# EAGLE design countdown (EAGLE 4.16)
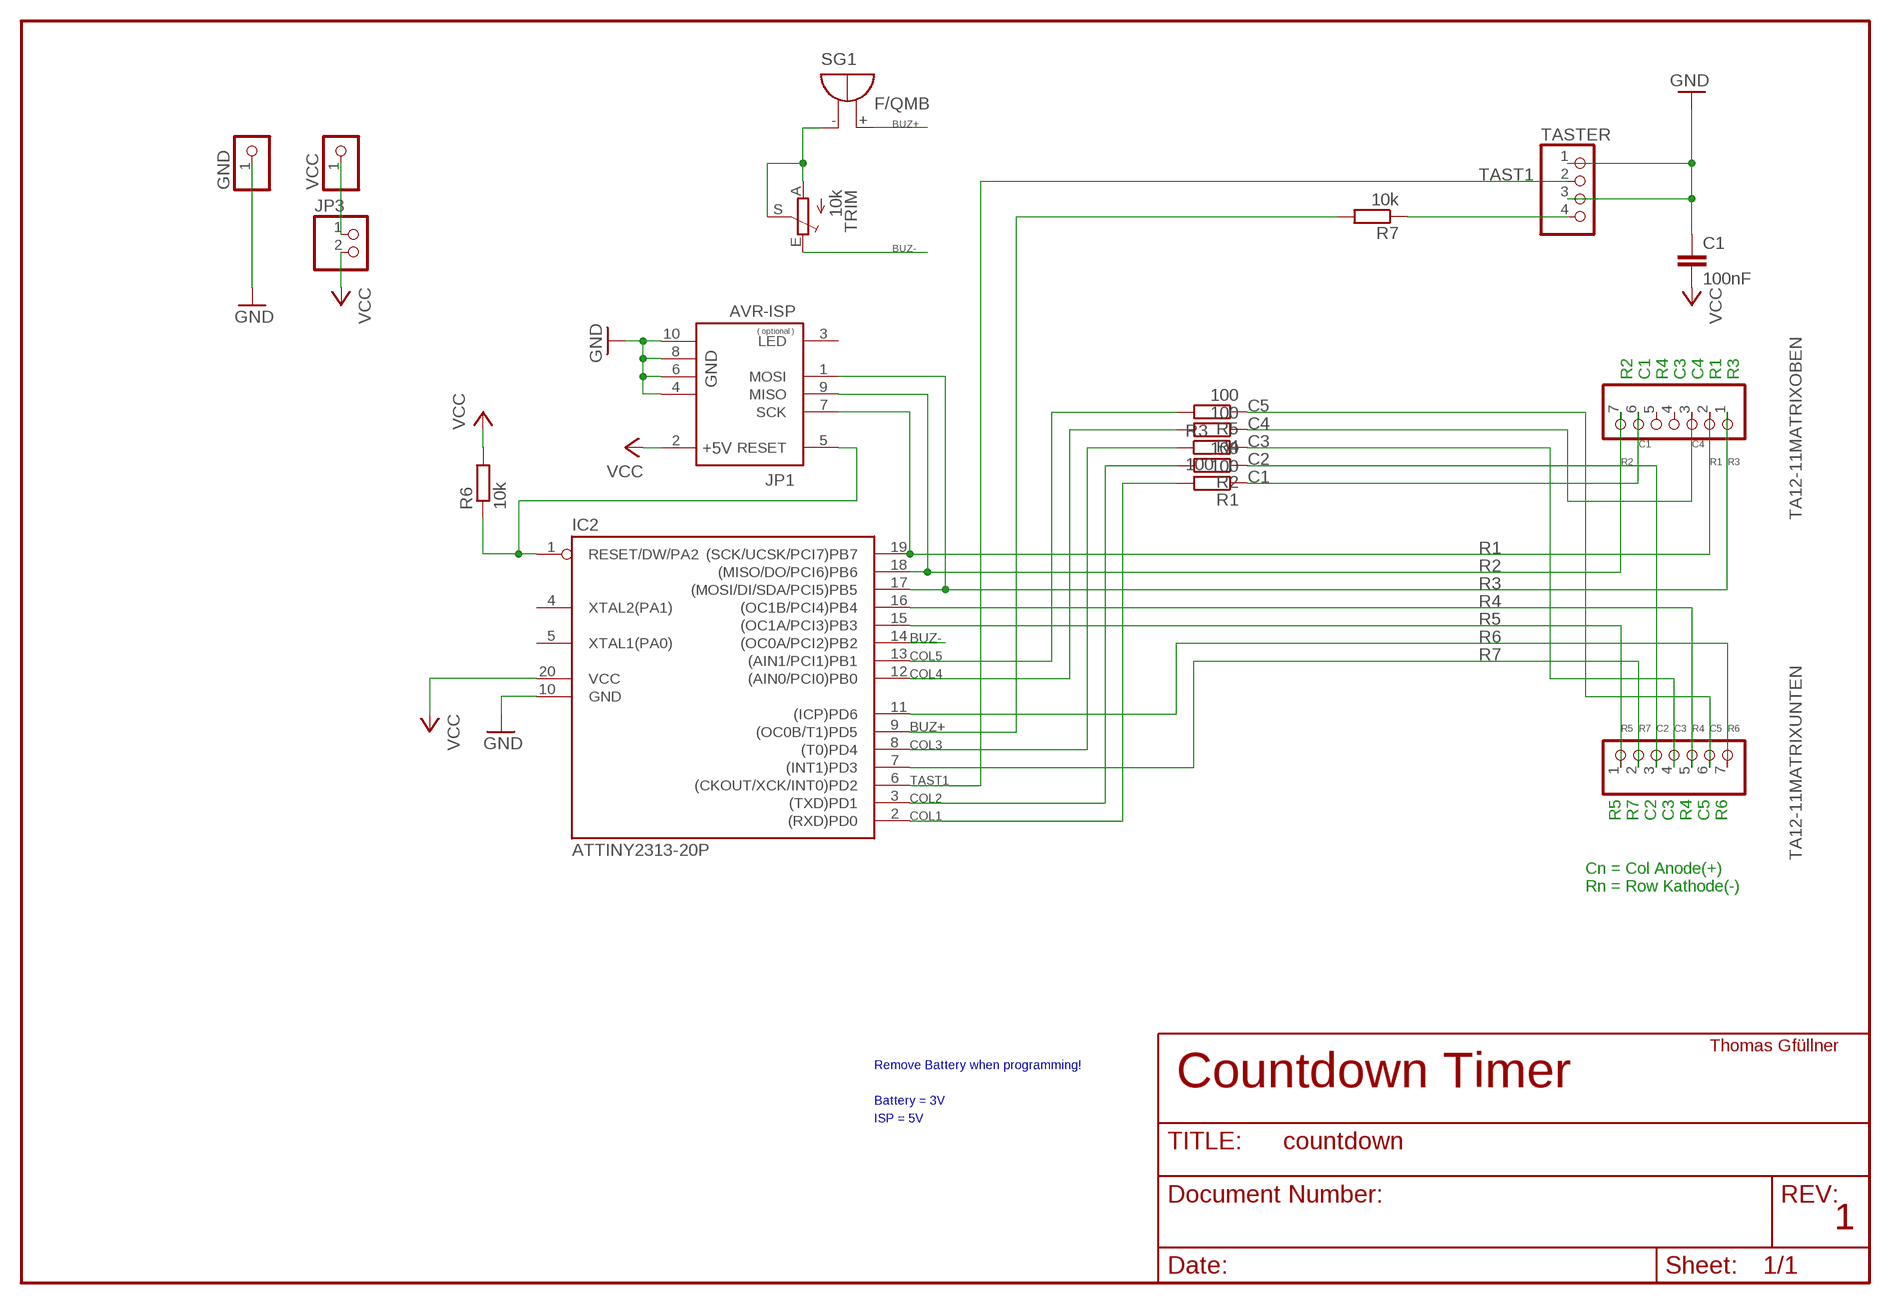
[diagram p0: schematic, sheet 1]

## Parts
C1  100nF  C-EU050-025X075  [C050-025X075]
GND  PINHD-1X1  [1X01]
IC2  ATTINY2313-20P  [DIL20]
JP1  AVR-ISP  [ML10]
JP3  PINHD-1X2  [1X02]
R1  100  R-EU_0207/12  [0207/12]
R2  100  R-EU_0207/12  [0207/12]
R3  100  R-EU_0204/7  [0204/7]
R4  100  R-EU_0207/12  [0207/12]
R5  100  R-EU_0207/12  [0207/12]
R6  10k  R-EU_0204/7  [0204/7]
R7  10k  R-EU_0207/12  [0207/12]
SG1  F/QMB  [F/QMB]
TA12-11MATRIXOBEN  PINHD-1X7  [1X07]
TA12-11MATRIXUNTEN  PINHD-1X7  [1X07]
TASTER  PINHD-1X4  [1X04]
TRIM  10k  TRIM_EU-S75H  [S75H]
VCC  PINHD-1X1  [1X01]

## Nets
BUZ+: IC2.9((OC0B/T1)PD5) R7.2 SG1.+(-)
BUZ-: IC2.14((OC0A/PCI2)PB2) TRIM.E
C1: R1.1 TA12-11MATRIXOBEN.6
C2: R2.1 TA12-11MATRIXUNTEN.3
C3: R3.2 TA12-11MATRIXUNTEN.4
C4: R4.1 TA12-11MATRIXOBEN.3
C5: R5.1 TA12-11MATRIXUNTEN.6
COL1: IC2.2((RXD)PD0) R1.2
COL2: IC2.3((TXD)PD1) R2.2
COL3: IC2.8((T0)PD4) R3.1
COL4: IC2.12((AIN0/PCI0)PB0) R4.2
COL5: IC2.13((AIN1/PCI1)PB1) R5.2
GND: C1.1 GND.1 IC2.10(GND) JP1.4(GND) JP1.6(GND) JP1.8(GND) JP1.10(GND) TASTER.1 TASTER.3
N$7: SG1.-(+) TRIM.A TRIM.S
N$9: IC2.1(RESET/DW/PA2) JP1.5(RESET) R6.1
N$10: R7.1 TASTER.4
N$27: JP3.1 VCC.1
R1: IC2.19((SCK/UCSK/PCI7)PB7) JP1.7(SCK) TA12-11MATRIXOBEN.2
R2: IC2.18((MISO/DO/PCI6)PB6) JP1.9(MISO) TA12-11MATRIXOBEN.7
R3: IC2.17((MOSI/DI/SDA/PCI5)PB5) JP1.1(MOSI) TA12-11MATRIXOBEN.1
R4: IC2.16((OC1B/PCI4)PB4) TA12-11MATRIXUNTEN.5
R5: IC2.15((OC1A/PCI3)PB3) TA12-11MATRIXUNTEN.1
R6: IC2.11((ICP)PD6) TA12-11MATRIXUNTEN.7
R7: IC2.7((INT1)PD3) TA12-11MATRIXUNTEN.2
TAST1: IC2.6((CKOUT/XCK/INT0)PD2) TASTER.2
VCC: C1.2 IC2.20(VCC) JP1.2(+5V) JP3.2 R6.2
Unconnected: IC2.4(XTAL2(PA1)) IC2.5(XTAL1(PA0)) JP1.3(LED) TA12-11MATRIXOBEN.4 TA12-11MATRIXOBEN.5

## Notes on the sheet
- R2 | C1 | R4 | C3 | C4 | R1 | R3
- R5 | R7 | C2 | C3 | R4 | C5 | R6
- Cn = Col Anode(+)
- Rn = Row Kathode(-)
- Thomas Gfüllner
- Remove Battery when programming!
- Countdown Timer
- Battery = 3V
- ISP = 5V
- 1

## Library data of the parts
C1 = rcl:C-EU: CAPACITOR, European symbol
GND VCC = pinhead:PINHD-1X1: PIN HEADER
IC2 = avr:ATTINY2313: MICROCONTROLLER 2 Kbytes FLASH 128 bytes SRAM 128 bytes EEPROM USART USI
JP1 = roboternetz-definitionen:AVR-ISP: ISP ( In System Programming ) Stecker für AVRs Über diesen Anschluß kann ein AVR mit einem Standard ISP-Kabel direkt an einen Parallelport des PC´s angeschlossen und programmiert werden. Die Belegung des ISP-Anschlusses ist zu dem weit verbreitetet STK200 Programmier Dongle kompatibel. Ein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
JP3 = pinhead:PINHD-1X2: PIN HEADER
R1-R7 = rcl:R-EU_: RESISTOR, European symbol
SG1 = buzzer:F/QMB: BUZZER
TA12-11MATRIXOBEN TA12-11MATRIXUNTEN = pinhead:PINHD-1X7: PIN HEADER
TASTER = pinhead:PINHD-1X4: PIN HEADER
TRIM = pot:TRIM_EU-: POTENTIOMETER

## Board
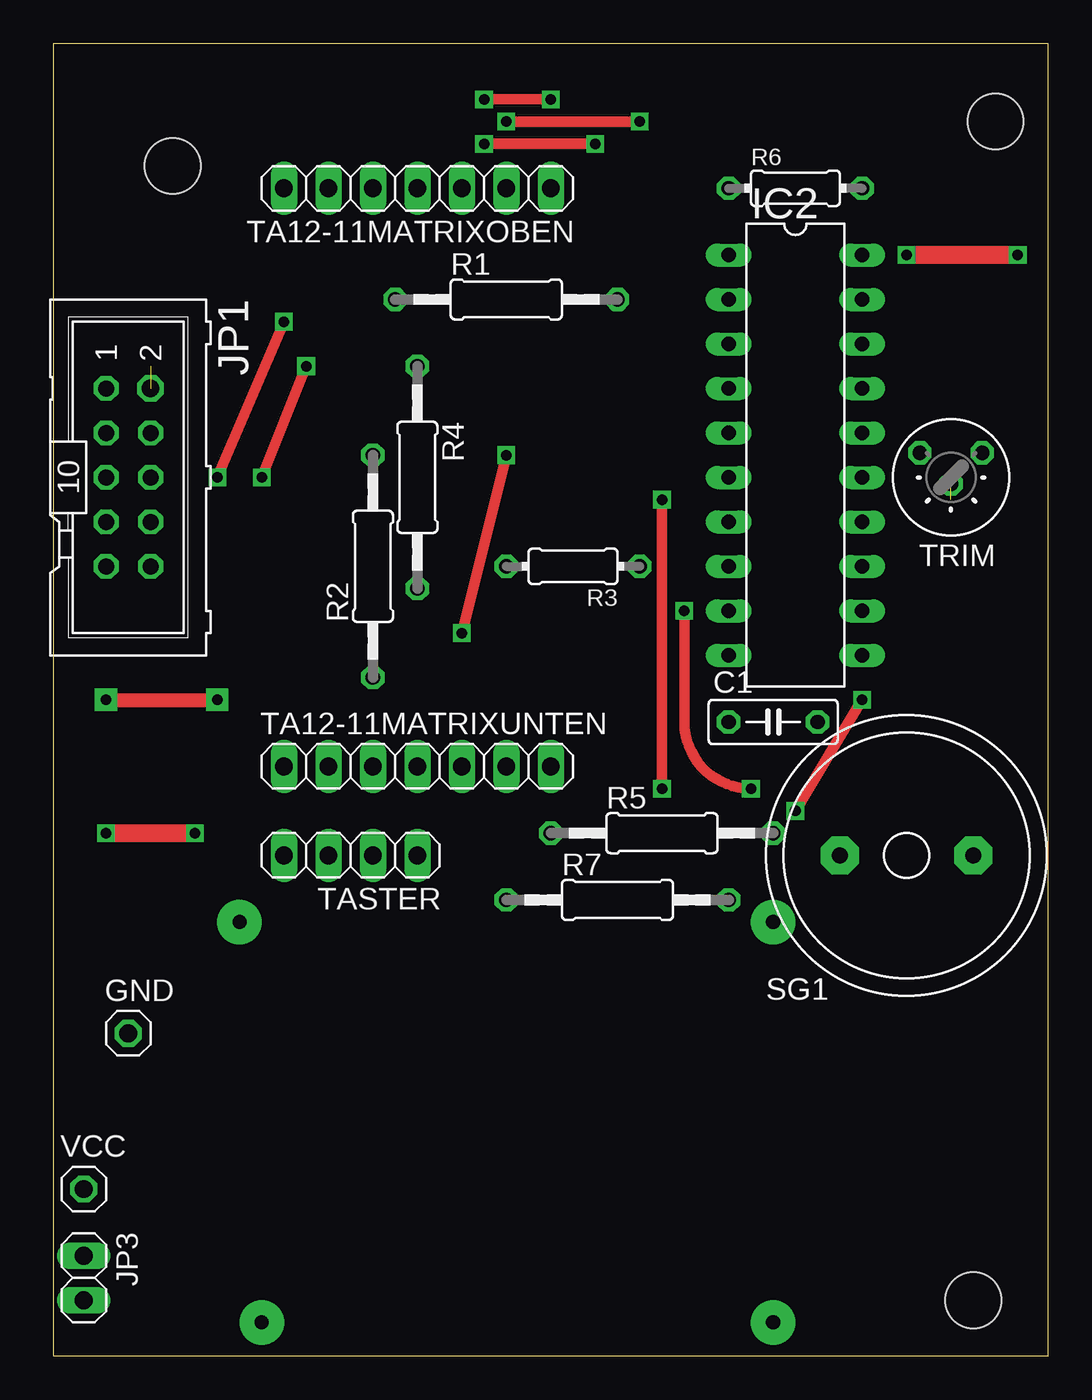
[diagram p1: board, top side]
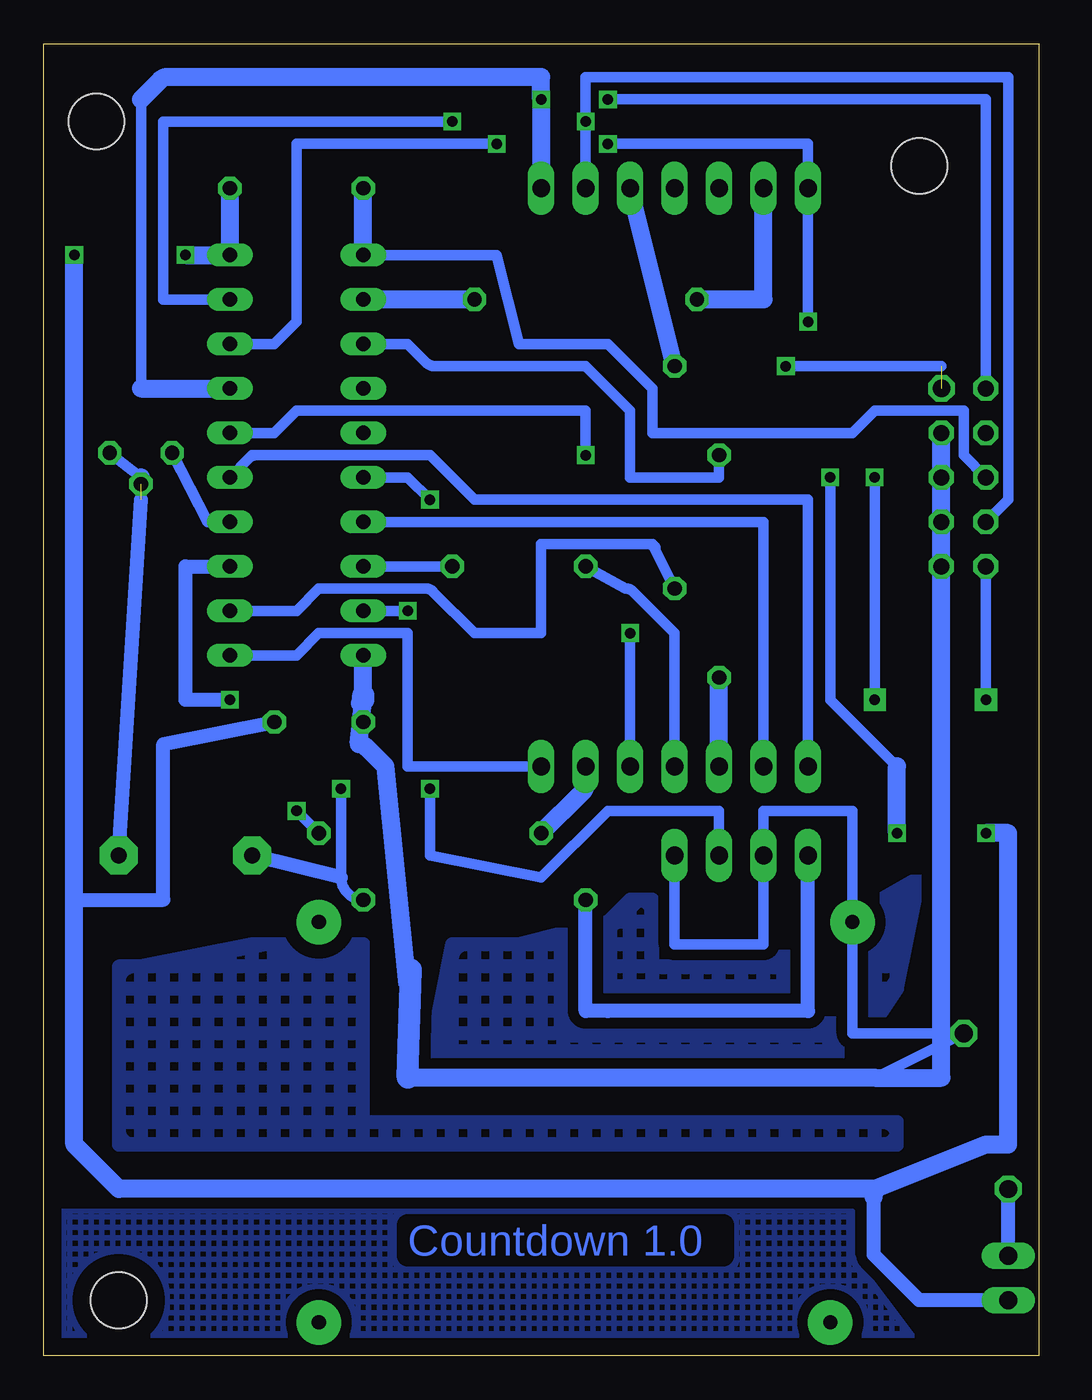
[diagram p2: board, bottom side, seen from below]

Size 56.82 x 74.92 mm. Coordinates in mm from the lower left corner, seen from the top.
Outline: 0,0 56.82,0 56.82,74.92 0,74.92 0,0
Copper layers (1*16): Top 0.035mm / dielectric 1.5mm / Bottom 0.035mm
Design rules "default": minimum track width 10mil, minimum drill 24mil, track to track 8mil, track to pad 8mil, pad to pad 8mil, via to via 8mil, smd to smd 8mil, copper to edge 40mil, drill to drill 8mil, minimum pad ring 10mil, minimum via ring 8mil, stop-mask expansion 4mil, vias tented up to drill 0mil, thermal gap 10mil
Holes 3.2 mm at 52.54,3.17 53.81,70.48 6.82,67.94

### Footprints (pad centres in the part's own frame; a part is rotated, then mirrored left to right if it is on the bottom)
C050-025X075 = drill 0.813 octagon: 1 -2.54,0; 2 2.54,0
1X01 = drill 1.016 octagon: 1 0,0
DIL20 = drill 0.813 long: 1 -11.43,-3.81; 2 -8.89,-3.81; 3 -6.35,-3.81; 4 -3.81,-3.81; 5 -1.27,-3.81; 6 1.27,-3.81; 7 3.81,-3.81; 8 6.35,-3.81; 9 8.89,-3.81; 10 11.43,-3.81; 11 11.43,3.81; 12 8.89,3.81; 13 6.35,3.81; 14 3.81,3.81; 15 1.27,3.81; 16 -1.27,3.81; 17 -3.81,3.81; 18 -6.35,3.81; 19 -8.89,3.81; 20 -11.43,3.81
ML10 = drill 0.914 pad 1.422 octagon: 1 -5.08,-1.27; 3 -2.54,-1.27; 4 -2.54,1.27 | drill 1.016 pad 1.422 octagon: 2 -5.08,1.27 | drill 0.914 octagon: 5 0,-1.27; 6 0,1.27; 7 2.54,-1.27; 8 2.54,1.27; 9 5.08,-1.27; 10 5.08,1.27
1X02 = drill 1.016 long: 1 -1.27,0; 2 1.27,0
0207/12 = drill 0.813 octagon: 1 -6.35,0; 2 6.35,0
0204/7 = drill 0.813 octagon: 1 -3.81,0; 2 3.81,0
F/QMB = drill 0.914 pad 2.159 octagon: + 3.81,0; - -3.81,0
1X07 = drill 1.016 long: 1 -7.62,0; 2 -5.08,0; 3 -2.54,0; 4 0,0; 5 2.54,0; 6 5.08,0; 7 7.62,0
1X04 = drill 1.016 long: 1 -3.81,0; 2 -1.27,0; 3 1.27,0; 4 3.81,0
S75H = drill 0.813 octagon: A -1.778,-1.397; E 1.778,-1.397; S 0,0.381

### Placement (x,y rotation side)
C1  41.11,36.19 0 top
GND  4.28,18.41 0 top
IC2  42.38,51.43 270 top
JP1  4.28,50.16 270 top
JP3  1.74,4.44 270 top
R1  25.87,60.32 0 top
R2  18.25,45.08 90 top
R3  29.68,45.08 180 top
R4  20.79,50.16 270 top
R5  34.76,29.84 0 top
R6  42.38,66.67 0 top
R7  32.22,26.03 0 top
SG1  48.73,28.57 180 top
TA12-11MATRIXOBEN  20.79,66.67 180 top
TA12-11MATRIXUNTEN  20.79,33.65 0 top
TASTER  16.98,28.57 180 top
TRIM  51.27,50.16 180 top
VCC  1.74,9.52 0 top

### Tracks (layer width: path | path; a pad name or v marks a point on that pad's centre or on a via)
BUZ+  (via drill 0.6 pad 0.3)
  Top 0.61: v36.03,42.54 36.03,36.19 arc90 v39.84,32.38
  Bottom 0.61: v36.03,42.54 IC2.9 | v39.84,32.38 39.84,27.3 arc-90 R7.2
  Bottom 0.813: 39.84,27.3 SG1.+
BUZ-
  Bottom 0.61: TRIM.E 47.46,47.62 IC2.14
C1
  Bottom 1.016: R1.1 15.71,60.32 TA12-11MATRIXOBEN.6
C2
  Bottom 1.016: TA12-11MATRIXUNTEN.3 R2.1
C3
  Bottom 0.61: TA12-11MATRIXUNTEN.4 20.79,41.27 23.14,43.62 arc-45 23.59,43.81 R3.2
C4
  Bottom 1.016: R4.1 TA12-11MATRIXOBEN.3
C5
  Bottom 1.016: R5.1 26.06,32.19 arc-45 25.87,32.64 TA12-11MATRIXUNTEN.6
COL1
  Bottom 1.016: R1.2 IC2.2
COL2
  Bottom 0.61: IC2.3 36.03,57.78 34.95,56.7 arc-45 34.5,56.51 25.87,56.51 23.33,53.97 23.33,50.16 18.25,50.16 R2.2
COL3
  Bottom 0.61: R3.1 IC2.8
COL4
  Bottom 0.61: 22.32,46.35 arc45 21.87,46.16 | 22.32,46.35 28.41,46.35 28.41,41.27 32.22,41.27 34.57,43.62 arc-45 35.02,43.81 41.11,43.81 42.38,42.54 IC2.12 | 22.32,46.35 22.06,46.35 R4.2
COL5  (via drill 0.6 pad 0.3)
  Top 0.61: v42.38,31.11 v46.19,37.46
  Bottom 0.61: R5.2 v42.38,31.11
  Bottom 0.813: v46.19,37.46 48.73,37.46 48.73,45.08 IC2.13
GND
  Bottom 0.61: 9.36,15.87 GND.1 10.63,18.41 10.63,31.11 15.71,31.11 TASTER.3 15.71,23.49 20.79,23.49 TASTER.1
  Bottom 1.016: 38.76,37.27 arc-45 38.57,37.72 IC2.10 | 35.84,22.03 arc45 36.03,21.21 37.3,33.65 38.38,34.73 arc-45 38.83,34.92 38.7,36.2 | 36.03,15.87 9.36,15.87 5.55,15.87 JP1.10 JP1.8 JP1.6 JP1.4 | 38.7,36.2 38.57,37.46 | 38.7,36.2 C1.1
  Bottom 1.27: 36.03,15.87 35.84,22.03 | 38.57,37.46 38.57,37.72
N$1  (via drill 0.6 pad 0.3)
  other vias: 23.33,41.27
N$2  (via drill 0.6 pad 0.3)
  other vias: 34.76,48.89
N$3  (via drill 0.6 pad 0.3)
  other vias: 34.76,32.38
N$4  (via drill 0.6 pad 0.3)
  other vias: 36.03,42.54
N$5  (via drill 0.6 pad 0.3)
  other vias: 39.84,32.38
N$6  (via drill 0.6 pad 0.3)
  other vias: 46.19,37.46
N$7  (1 unrouted)
  Bottom 0.61: 51.27,50.16 TRIM.A
  Bottom 0.813: SG1.- 51.27,48.89
  Bottom 1.016: TRIM.S 51.27,50.16
N$8  (via drill 0.6 pad 0.3)
  other vias: 42.38,31.11
N$9
  Bottom 0.61: IC2.1 30.95,62.86 29.68,57.78 24.6,57.78 22.06,55.24 22.06,52.7 10.63,52.7 9.36,53.97 4.28,53.97 4.28,51.43 JP1.5
  Bottom 1.016: IC2.1 R6.1
N$10
  Bottom 0.813: TASTER.4 13.17,19.68 24.6,19.68 25.87,19.68 R7.1
N$11  (via drill 0.6 pad 0.3)
  other vias: 48.73,62.86
N$12  (via drill 0.8 pad 2.54)
  other vias: 41.11,24.76
N$13  (via drill 0.6 pad 0.3)
  other vias: 9.36,50.16
N$14  (via drill 0.6 pad 0.3)
  other vias: 13.17,59.05
N$15  (via drill 0.6 pad 0.3)
  other vias: 24.6,71.75
N$16  (via drill 0.6 pad 0.3)
  other vias: 30.95,69.21
N$17  (via drill 0.6 pad 0.3)
  other vias: 24.6,69.21
N$18  (via drill 0.6 pad 0.3)
  other vias: 33.49,70.48
N$19  (via drill 0.6 pad 0.3)
  other vias: 11.9,50.16
N$20  (via drill 0.6 pad 0.3)
  other vias: 3.01,29.84
N$21  (via drill 0.8 pad 2.54)
  other vias: 41.11,1.9
N$22  (via drill 0.8 pad 2.54)
  other vias: 10.63,24.76
N$23  (via drill 0.8 pad 2.54)
  other vias: 11.9,1.9
N$24
  pour Bottom (isolate 0.813, rank 2, hatched): 8.09,13.33 38.57,13.33 38.57,23.49 44.92,23.49 51.27,22.22 52.54,22.22 52.54,12.06 8.09,12.06
N$25
  pour Bottom (isolate 0.61, hatched): 6.82,0.63 10.63,5.71 10.63,8.25 56.35,8.25 56.35,0.63
N$26
  pour Bottom (isolate 0.61, no thermals, hatched): 34.76,17.14 10.63,17.14 8.09,20.95 6.82,27.3 15.71,22.22 22.06,22.22 22.06,26.03 23.33,26.03 24.6,24.76 29.68,23.49 33.49,23.49
N$27
  Bottom 0.813: JP3.1 VCC.1
R1  (via drill 0.6 pad 0.3)
  Top 0.61: v25.87,70.48 v33.49,70.48
  Bottom 0.61: JP1.7 1.74,48.89 1.74,73.02 25.87,73.02 v25.87,70.48 TA12-11MATRIXOBEN.2 | IC2.19 50,60.32 50,70.48 v33.49,70.48
R2  (via drill 0.6 pad 0.3, 0.6 pad 1.27)
  Top 0.61: v9.36,50.16 v13.17,59.05 | v24.6,69.21 v30.95,69.21
  Top 0.813: v3.01,37.46 v9.36,37.46
  Bottom 0.61: IC2.18 43.65,57.78 42.38,59.05 42.38,69.21 v30.95,69.21 | v3.01,37.46 JP1.9 | v9.36,37.46 v9.36,50.16 | v13.17,59.05 TA12-11MATRIXOBEN.7 13.17,69.21 v24.6,69.21
R3  (via drill 0.6 pad 0.3)
  Top 0.61: v24.6,71.75 v28.41,71.75
  Bottom 0.61: 51.27,71.75 51.27,55.24 | JP1.1 3.01,71.75 v24.6,71.75
  Bottom 1.016: 51.27,55.24 IC2.17 | 51.27,71.75 50.19,72.83 arc45 49.74,73.02 28.41,73.02 v28.41,71.75 TA12-11MATRIXOBEN.1
R4  (via drill 0.6 pad 0.3)
  Top 0.61: v23.33,41.27 v25.87,51.43
  Bottom 0.61: IC2.16 43.65,52.7 42.38,53.97 25.87,53.97 v25.87,51.43 | TA12-11MATRIXUNTEN.5 v23.33,41.27
R5
  Bottom 0.61: IC2.15 45.11,51.24 arc45 44.66,51.43 | TA12-11MATRIXUNTEN.1 13.17,48.89 32.22,48.89 34.76,51.43 44.66,51.43 | 44.66,51.43 44.92,51.43
R6
  Bottom 0.61: IC2.11 42.38,40 41.11,41.27 36.03,41.27 36.03,33.65 TA12-11MATRIXUNTEN.7
R7
  Bottom 0.61: IC2.7 15.71,47.62 TA12-11MATRIXUNTEN.2
TAST1  (via drill 0.6 pad 0.3)
  Top 0.61: v34.76,32.38 v34.76,48.89
  Bottom 0.61: IC2.6 36.03,50.16 v34.76,48.89 | v34.76,32.38 34.76,28.57 28.41,27.3 24.6,31.11 18.25,31.11 TASTER.2
VCC  (via drill 0.6 pad 0.3)  (1 unrouted)
  Top 0.61: v11.9,50.16 v14.44,56.51
  Top 1.016: v55.08,62.86 v48.73,62.86 | v3.01,29.84 v8.09,29.84
  Bottom 0.61: v14.44,56.51 5.55,56.51 | v11.9,50.16 11.9,37.46 8.09,33.65
  Bottom 0.813: 55.08,26.03 50,26.03 50,34.92 C1.2 | 9.42,9.05 9.42,5.77 6.82,3.17 JP3.2
  Bottom 1.016: R6.2 IC2.20 v48.73,62.86 | v55.08,62.86 55.08,26.03 55.08,12.06 52.54,9.52 9.36,9.52 | v8.09,29.84 8.09,33.65 | 9.42,9.05 9.36,9.52 | 9.36,9.52 3.01,12.06 1.74,12.06 1.74,29.84 v3.01,29.84

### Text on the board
Bottom: Countdown 1.0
